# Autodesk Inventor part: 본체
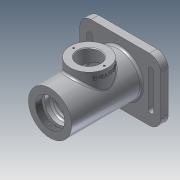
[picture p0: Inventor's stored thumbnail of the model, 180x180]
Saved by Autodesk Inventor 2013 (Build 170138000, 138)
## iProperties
Created: 2021-07
Part Number: 본체
Material: 알루미늄 6061
Document SubType Name: Modeling
Designer: kumcom3
Density: 2.71 g/cm^3
Mass: 755.343 g
Surface Area: 649.246 cm^2
Volume: 278.724 cm^3
Author: kumcom3
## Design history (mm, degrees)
sketch "스케치1"
  geometry: C1 r 31 at (0, 0); 1 further point
  constraints: 1 centre point, 1 coincident
  dimensions: "d0" = 62 diameter of C1
extrude "돌출1" new body sketch "스케치1" stored distance "d2" = 115; taper "d3" = 0 deg
node "작업 평면1"
sketch "스케치2"
  geometry: L1 (-58, 45)-(58, 45); L2 (58, 45)-(58, -45); L3 (58, -45)-(-58, -45); L4 (-58, -45)-(-58, 45); C1 r 31 at (0, 0) reference; 3 further points
  constraints: 8 end point, 2 midpoint, 2 parallel, 1 horizontal, 1 horizontal alignment, 1 perpendicular, 1 vertical alignment
  dimensions: "d5" = 116 distance of L1.start L1.end; "d7" = 90 distance of L3.end L1.start
extrude "돌출2" join sketch "스케치2" distance "d8" = 11; taper "d9" = 0 deg
sketch "스케치3"
  geometry: L1 (31, -43.5)-(-31, -43.5) reference; L2 (31, 57.5)-(-31, 57.5) reference; C1 r 27 at (0, 1.5); 2 further points
  constraints: 1 centre point, 1 coincident, 1 midpoint, 1 vertical alignment
  dimensions: "d10" = 54 diameter of C1; "d91" = 56 distance from line of point (0, 1.5) L2
extrude "돌출3" join sketch "스케치3" distance "d12" = 42; taper "d13" = 0 deg
sketch "스케치4"
  geometry: L1 (0, 65.157)-(0, -68.283); L2 (0, 57.5)-(21, 57.5); L3 (21, 57.5)-(21, 48.5); L4 (21, 48.5)-(0, 48.5); L5 (0, 48.5)-(0, 57.5); L6 (0, 48.5)-(24, 48.5); L7 (24, 48.5)-(24, 45.5); L8 (24, 45.5)-(0, 45.5); L9 (0, 45.5)-(0, 48.5); L10 (0, 45.5)-(20, 45.5); L11 (20, 45.5)-(20, 36.5); L12 (20, 36.5)-(0, 36.5); L13 (0, 36.5)-(0, 45.5); L14 (0, 36.5)-(17.5, 36.5); L15 (17.5, 36.5)-(17.5, 20.5); L16 (17.5, 20.5)-(0, 20.5); L17 (0, 20.5)-(0, 36.5); L18 (0, 20.5)-(26, 20.5); L19 (26, 20.5)-(26, -17.5); L20 (26, -17.5)-(0, -17.5); L21 (0, -17.5)-(0, 20.5); L22 (0, -17.5)-(17.5, -17.5); L23 (17.5, -17.5)-(17.5, -28.5); L24 (17.5, -28.5)-(0, -28.5); L25 (0, -28.5)-(0, -17.5); L26 (0, -28.5)-(16, -28.5); L27 (16, -28.5)-(16, -33.5); L28 (16, -33.5)-(0, -33.5); L29 (0, -33.5)-(0, -28.5); L30 (0, -33.5)-(10, -33.5); L31 (10, -33.5)-(10, -36.2); L32 (10, -36.2)-(0, -36.2); L33 (0, -36.2)-(0, -33.5); L34 (0, -36.2)-(12.5, -36.2); L35 (12.5, -36.2)-(12.5, -43.5); L36 (12.5, -43.5)-(0, -43.5); L37 (0, -43.5)-(0, -36.2); L38 (12.5, -43.5)-(16, -43.5); L39 (16, -43.5)-(22, -57.5); L40 (22, -57.5)-(0, -57.5); L41 (31, 57.5)-(-31, 57.5) reference; L42 (-31, -57.5)-(31, -57.5) reference; L43 (0, 33.25)-(18.5, 33.25); L44 (18.5, 33.25)-(18.5, 31.5); L45 (18.5, 31.5)-(0, 31.5); L46 (0, 31.5)-(0, 33.25); L47 (22, -57.5)-(0, -57.5); L48 (0, -43.5)-(0, -57.5); 1 further point
  constraints: 92 end point, 20 parallel, 12 perpendicular, 10 horizontal, 4 collinear, 4 point on line, 1 vertical
  dimensions: "d14" = 9 distance between parallel lines of L4 L41; "d15" = 3 distance between parallel lines of L8 L6; "d16" = 21 distance between parallel lines of L12 L2; "d17" = 38 distance between parallel lines of L20 L18; "d18" = 14 distance between parallel lines of L38 L42; "d19" = 7.3 distance between parallel lines of L36 L34; "d20" = 24 distance between parallel lines of L40 L30; "d21" = 11 distance between parallel lines of L24 L20; "d22" = 65 distance between parallel lines of L26 L12; "d23" = 42 diameter of L3 L1; "d24" = 48 diameter of L7 L1; "d25" = 40 diameter of L11 L13; "d26" = 35 diameter of L15 L17; "d27" = 52 diameter of L19 L1; "d28" = 35 diameter of L23 L1; "d29" = 32 diameter of L27 L1; "d30" = 20 diameter of L31 L33; "d31" = 25 diameter of L35 L1; "d32" = 44 diameter of L39.end L1; "d33" = 32 diameter of L38.end L1; "d34" = 1.75 distance between parallel lines of L45 L43; "d35" = 37 diameter of L44 L1; "d36" = 11 distance between parallel lines of L16 L45
revolve "회전1" sketch "스케치4" stored, may be unused: angle "d37" = 90 deg
sketch "스케치5"
  geometry: L1 (0, 0)-(0, -87.301); L2 (-31, -57.5)-(31, -57.5) reference; L3 (12.5, -43.5)-(-12.5, -43.5) reference; L4 (0, -43.5)-(16, -43.5); L5 (16, -43.5)-(22, -57.5); L6 (22, -57.5)-(0, -57.5); L7 (0, -57.5)-(0, -43.5)
  constraints: 10 end point, 2 collinear, 2 midpoint, 1 point on line, 1 vertical
  dimensions: "d38" = 32 diameter of L4.end L1; "d40" = 44 diameter of L5.end L1
revolve "회전2" sketch "스케치5" stored, may be unused: angle "d41" = 90 deg
sketch "스케치6"
  geometry: L1 (58, -45)-(58, 45) reference; L2 (-48, 25)-(-48, -25); L3 (-40, 25)-(-40, -25); C1 r 31 at (0, 0) reference; A1 r 4 centre (-44, 25) between (-48, 25) and (-40, 25); A2 r 4 centre (-44, -25) between (-48, -25) and (-40, -25); 1 further point
  constraints: 4 end point, 4 point on circle, 3 tangent, 2 centre point, 1 equal radius, 1 horizontal alignment, 1 midpoint, 1 parallel, 1 vertical alignment
  dimensions: "d42" = 8 diameter of A1; "d44" = 44 horizontal distance of C1.centre A1.centre; "d45" = 50 distance of A2.centre A1.centre
extrude "돌출4" cut sketch "스케치6" distance "d46" = 42; taper "d47" = 0 deg
hole "구멍1" diameter "d50" = 32; stored, may be unused: countersink angle "d54" = 90 deg, drill point angle "d56" = 118 deg; dims "d48" = 10, "d49" = 10, "d51" = 6, "d52" = 4, "d53" = 2, "d55" = 20.7
feature "스레드1" dims "d57" = 10, "d58" = 0
fillet "모깎기1" dims "d59" = 3
chamfer "모따기1" distance "d60" = 1; stored, may be unused: second distance "d61" = 2, angle "d62" = 45 deg
fillet "모깎기2" dims "d63" = 0.3
fillet "모깎기3" dims "d64" = 3
fillet "모깎기4" dims "d65" = 0.3
chamfer "모따기2" distance "d66" = 0.7; stored, may be unused: second distance "d67" = 2, angle "d68" = 30 deg
fillet "모깎기5" dims "d69" = 3
chamfer "모따기3" distance "d70" = 1; stored, may be unused: second distance "d71" = 2, angle "d72" = 30 deg
fillet "모깎기6" dims "d73" = 16
fillet "모깎기7" dims "d74" = 3
sketch "스케치7" dims "d75" = 44
  geometry: C1 r 27 at (0, 0) reference; C2 r 17 at (0, 0) reference; 2 further points
  constraints: 2 horizontal alignment, 1 coincident, 2 other
hole "구멍2" sketch "스케치7" at (-22, 0) diameter "d77" = 2.459; stored, may be unused: countersink angle "d81" = 90 deg, drill point angle "d83" = 118 deg; dims "d78" = 6, "d79" = 4, "d80" = 2, "d82" = 8
node "작업 평면2"
sketch "스케치8"
  geometry: L1 (31, 56)-(-31, 56) reference; L2 (42, -27)-(42, 27) reference; 2 further points
  constraints: 1 other
  dimensions: "d87" = 58 distance from line of point (34, -2) L1; "d88" = 8 distance from line of point (34, -2) L2
feature "엠보싱1" sketch "스케치8" dims "d3" = 0, "d89" = 0.5, "d90" = 0
sketch "스케치9"
  geometry: C1 r 31 at (0, 0) reference; C2 r 35 at (0, 0)
  constraints: 1 centre point, 1 coincident
  dimensions: "d92" = 70 diameter of C2
extrude "돌출5" join sketch "스케치9" stored distance "d94" = 0; taper "d95" = 0 deg
node "솔리드1"
mirror "대칭1"
pattern_circular "원형 패턴1" dims angle "d85" = 360 deg
node "투영된 루프1"
node "투영된 루프2"
other parameters: "d4" = -54.5
